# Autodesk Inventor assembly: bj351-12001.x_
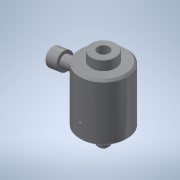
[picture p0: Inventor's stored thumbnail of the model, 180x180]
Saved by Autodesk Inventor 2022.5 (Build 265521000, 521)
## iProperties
Part Number: bj351-12001.x_
Material: 一般
Document SubType Name: Assembly
Designer: ImaoCorp
Sending System: SOLIDWORKS 2017-2017317
MC: AMD64
MC_MODEL: Intel64 Family 6 Model 60 Stepping 3, GenuineIntel
OS: Windows_NT
FRU: Parasolid Version 29.0, build 201,  4-17-2017
FORMAT: text
GUISE: transmit
KEY: bj351-12001
FILE: bj351-12001.x_t
DATE: Fri Mar 15 10:12:31 2019
Author: ImaoCorp
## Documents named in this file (4)
- X:\14_SW2022-Inv2022\00_全2023-1023新製品(TCC)まで\b\bj351-12001\BJ351-12001.iam
- X:\14_SW2022-Inv2022\00_全2023-1023新製品(TCC)まで\b\bj351-12001\bj351-12001_01.ipt
- X:\14_SW2022-Inv2022\00_全2023-1023新製品(TCC)まで\b\bj351-12001\bj351-12001_02.ipt
- X:\14_SW2022-Inv2022\00_全2023-1023新製品(TCC)まで\b\bj351-12001\bj351-12001_03.ipt
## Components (3 placed, 3 different names)
1. bj351-12001_01
2. bj351-12001_02
3. bj351-12001_03
